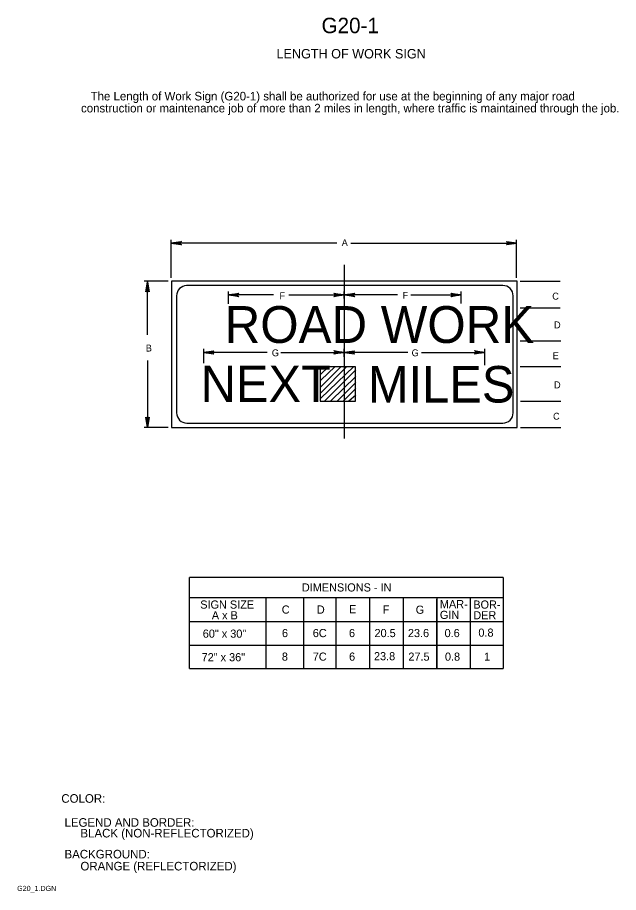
# Model space of a CAD drawing. Extents: x 0.013 to 0.188, y 0.004 to 0.259.
import ezdxf

# ---------------------------------------------------------------- set-up
doc = ezdxf.new("R2010")
doc.units = 0
for name, color, linetype in [('1', 7, 'Continuous'), ('2', 7, 'Continuous'), ('3', 7, 'Continuous')]:
    doc.layers.add(name, color=color, linetype=linetype)

# ---------------------------------------------------------------- blocks, each defined once
blk = doc.blocks.new('RARROW')
at = {"layer": '3'}
blk.add_lwpolyline([(-2.2695, 0.285), (-2.184875, 0.12075), (0, 0), (-2.2695, 0.285), (-2.38575, 0.384625), (0, 0), (-2.183125, -0.108), (-2.262875, -0.2705), (0, 0), (-2.38575, -0.379125), (-2.262875, -0.2705)], dxfattribs=at)

msp = doc.modelspace()

# ---------------------------------------------------------------- linework, layer by layer
at = {"layer": '3'}
for p, q in [((0.05738, 0.18325), (0.05738, 0.19437)), ((0.15813, 0.18325), (0.15813, 0.19437)), ((0.10575, 0.19337), (0.05738, 0.19337)), ((0.10975, 0.19337), (0.15813, 0.19337)), ((0.10787, 0.187), (0.10787, 0.13637)), ((0.0565, 0.18225), (0.0495, 0.18225)), ((0.0505, 0.16662), (0.0505, 0.18225)), ((0.15825, 0.18225), (0.0575, 0.18225)), ((0.0575, 0.18225), (0.0575, 0.13962)), ((0.15825, 0.13962), (0.15825, 0.18225)), ((0.15913, 0.18225), (0.17087, 0.18225)), ((0.15413, 0.181), (0.06187, 0.181)), ((0.07412, 0.17563), (0.07412, 0.17925)), ((0.10787, 0.17725), (0.10787, 0.17925)), ((0.142, 0.17575), (0.142, 0.17925)), ((0.059, 0.178), (0.059, 0.14387)), ((0.08725, 0.17825), (0.07412, 0.17825)), ((0.09175, 0.17825), (0.10787, 0.17825)), ((0.12337, 0.17825), (0.10787, 0.17825)), ((0.12725, 0.17825), (0.142, 0.17825)), ((0.15713, 0.14387), (0.15713, 0.178)), ((0.15913, 0.1745), (0.17087, 0.1745)), ((0.15913, 0.16487), (0.171, 0.16487)), ((0.06688, 0.15838), (0.06688, 0.1625)), ((0.08538, 0.1615), (0.06688, 0.1615)), ((0.08937, 0.1615), (0.10787, 0.1615)), ((0.10787, 0.16025), (0.10787, 0.1625)), ((0.12638, 0.1615), (0.10787, 0.1615)), ((0.13037, 0.1615), (0.14888, 0.1615)), ((0.14888, 0.15775), (0.14888, 0.1625)), ((0.0505, 0.15913), (0.0505, 0.13962)), ((0.11113, 0.15725), (0.10088, 0.15725)), ((0.10088, 0.15725), (0.10088, 0.14725)), ((0.101, 0.157), (0.10163, 0.15738)), ((0.101, 0.15513), (0.10338, 0.15738)), ((0.101, 0.15338), (0.10525, 0.15738)), ((0.101, 0.1515), (0.107, 0.15738)), ((0.101, 0.14975), (0.10862, 0.15738)), ((0.101, 0.14813), (0.11063, 0.15738)), ((0.10225, 0.14738), (0.11125, 0.15638)), ((0.11113, 0.14725), (0.11113, 0.15725)), ((0.15913, 0.15738), (0.171, 0.15738)), ((0.104, 0.14738), (0.11125, 0.1545)), ((0.10587, 0.14738), (0.11125, 0.15275)), ((0.10762, 0.14738), (0.11125, 0.151)), ((0.10925, 0.14738), (0.11125, 0.14913)), ((0.10088, 0.14725), (0.11113, 0.14725)), ((0.11125, 0.14738), (0.11125, 0.14738)), ((0.15925, 0.14725), (0.171, 0.14725)), ((0.062, 0.14088), (0.15413, 0.14088)), ((0.0565, 0.13962), (0.0495, 0.13962)), ((0.0575, 0.13962), (0.15825, 0.13962)), ((0.15925, 0.13962), (0.171, 0.13962)), ((0.06263, 0.09588), (0.06263, 0.06925)), ((0.15423, 0.09587), (0.06271, 0.09587)), ((0.15423, 0.09587), (0.15423, 0.06925)), ((0.15423, 0.08987), (0.06271, 0.08987)), ((0.08498, 0.08987), (0.08498, 0.06925)), ((0.096, 0.08987), (0.096, 0.06925)), ((0.10537, 0.08987), (0.10537, 0.06925)), ((0.11525, 0.08987), (0.11525, 0.06925)), ((0.125, 0.08987), (0.125, 0.06925)), ((0.13475, 0.0895), (0.13475, 0.06925)), ((0.13485, 0.08987), (0.13485, 0.06925)), ((0.1446, 0.08987), (0.1446, 0.06925)), ((0.06271, 0.083), (0.15423, 0.083)), ((0.06271, 0.07612), (0.15423, 0.07612)), ((0.06271, 0.06925), (0.15423, 0.06925))]:
    msp.add_line(p, q, dxfattribs=at)
for centre, radius, start, end in [((0.06196, 0.17804), 0.00296, 90.6987, 180.6987), ((0.15411, 0.17799), 0.00302, 0.1547, 90.1547), ((0.062, 0.14387), 0.003, 180, 270), ((0.15412, 0.14389), 0.00301, 269.7263, 359.7263)]:
    msp.add_arc(centre, radius, start, end, dxfattribs=at)

# ---------------------------------------------------------------- block references
at = {"layer": '3', "xscale": 0.0012574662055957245, "yscale": 0.001309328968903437}
for p, rotation in [((0.05738, 0.19337), 180), ((0.0505, 0.18213), 90), ((0.07412, 0.17825), 180), ((0.10787, 0.17825), 180), ((0.06688, 0.1615), 180), ((0.10787, 0.1615), 180), ((0.0505, 0.13962), -90)]:
    msp.add_blockref('RARROW', p, dxfattribs=dict(at, rotation=rotation))
for p in [(0.15813, 0.19337), (0.10787, 0.17825), (0.142, 0.17825), (0.10787, 0.1615), (0.14888, 0.1615)]:
    msp.add_blockref('RARROW', p, dxfattribs=at)

# ---------------------------------------------------------------- texts
at = {"layer": '1'}
for s, height, p in [('G20-1', 0.0045, (0.10125, 0.25462)), ('LENGTH OF WORK SIGN', 0.0027503, (0.08812, 0.24725)), ('COLOR:', 0.0025, (0.02538, 0.03012)), (' LEGEND AND BORDER:', 0.0024998, (0.02538, 0.02312)), ('      BLACK (NON-REFLECTORIZED)', 0.0024998, (0.02538, 0.02)), (' BACKGROUND:', 0.0024998, (0.02538, 0.01388)), ('      ORANGE (REFLECTORIZED)', 0.0024998, (0.02538, 0.01038)), ('G20_1.DGN', 0.0015, (0.0125, 0.00438))]:
    msp.add_text(s, height=height, dxfattribs=at).set_placement(p)
at = {"layer": '2'}
for s, height, p in [('   The Length of Work Sign (G20-1) shall be authorized for use at the beginning of any major road', 0.0024998, (0.03112, 0.235)), ('construction or maintenance job of more than 2 miles in length, where traffic is maintained through the job.', 0.00249975, (0.03112, 0.2315))]:
    msp.add_text(s, height=height, dxfattribs=at).set_placement(p)
at = {"layer": '3'}
for s, height, p in [('A', 0.002, (0.10712, 0.1925)), ('F', 0.002, (0.089, 0.177)), ('F', 0.002, (0.12487, 0.17713)), ('C', 0.00204, (0.1685, 0.17688)), ('ROAD WORK', 0.01075, (0.073, 0.16425)), ('D', 0.00204, (0.169, 0.1685)), ('B', 0.002, (0.05, 0.16175)), ('G', 0.002, (0.08675, 0.16037)), ('G', 0.002, (0.1275, 0.16037)), ('E', 0.00204, (0.16862, 0.1595)), ('NEXT', 0.01065, (0.066, 0.147)), ('MILES', 0.01065, (0.11475, 0.14688)), ('D', 0.00204, (0.169, 0.151)), ('C', 0.002, (0.16875, 0.14188)), ('DIMENSIONS - IN', 0.0023752, (0.09551, 0.09175)), ('SIGN SIZE', 0.002375, (0.06588, 0.08675)), ('C', 0.00238, (0.08965, 0.08529)), ('D', 0.00238, (0.09988, 0.08529)), ('E', 0.00238, (0.10925, 0.08541)), ('F', 0.00238, (0.11906, 0.08529)), ('G', 0.00238, (0.12871, 0.08525)), ('MAR-', 0.002375, (0.13575, 0.08688)), ('BOR-', 0.002375, (0.1455, 0.08675)), ('A x B', 0.002375, (0.06925, 0.08363)), ('GIN', 0.002375, (0.13575, 0.08375)), ('DER', 0.002375, (0.1455, 0.08363)), ('60" x 30"', 0.002375, (0.06662, 0.07827)), ('6', 0.00238, (0.0897, 0.07844)), ('6C', 0.002375, (0.09869, 0.07844)), ('6', 0.00238, (0.10924, 0.07844)), ('20.5', 0.002375, (0.11669, 0.07844)), ('23.6', 0.002375, (0.12643, 0.07844)), ('0.6', 0.002375, (0.13712, 0.07844)), ('0.8', 0.002375, (0.14698, 0.07856)), ('23.8', 0.002375, (0.11654, 0.07169)), ('72" x 36"', 0.002375, (0.06628, 0.07139)), ('8', 0.00238, (0.08968, 0.07156)), ('7C', 0.002375, (0.09869, 0.07156)), ('6', 0.00238, (0.10927, 0.07156)), ('27.5', 0.002375, (0.12656, 0.07156)), ('0.8', 0.002375, (0.13723, 0.07156)), ('1', 0.00238, (0.14864, 0.07156))]:
    msp.add_text(s, height=height, dxfattribs=at).set_placement(p)

doc.saveas('drawing.dxf')
